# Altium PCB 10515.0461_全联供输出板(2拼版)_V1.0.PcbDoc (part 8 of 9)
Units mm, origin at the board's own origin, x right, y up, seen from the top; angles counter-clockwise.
Board outline 283.88 x 134.8 mm, 2 copper layers (Top Layer, Bottom Layer); 298 components, 0 nets, 1264 pads, 970 vias.
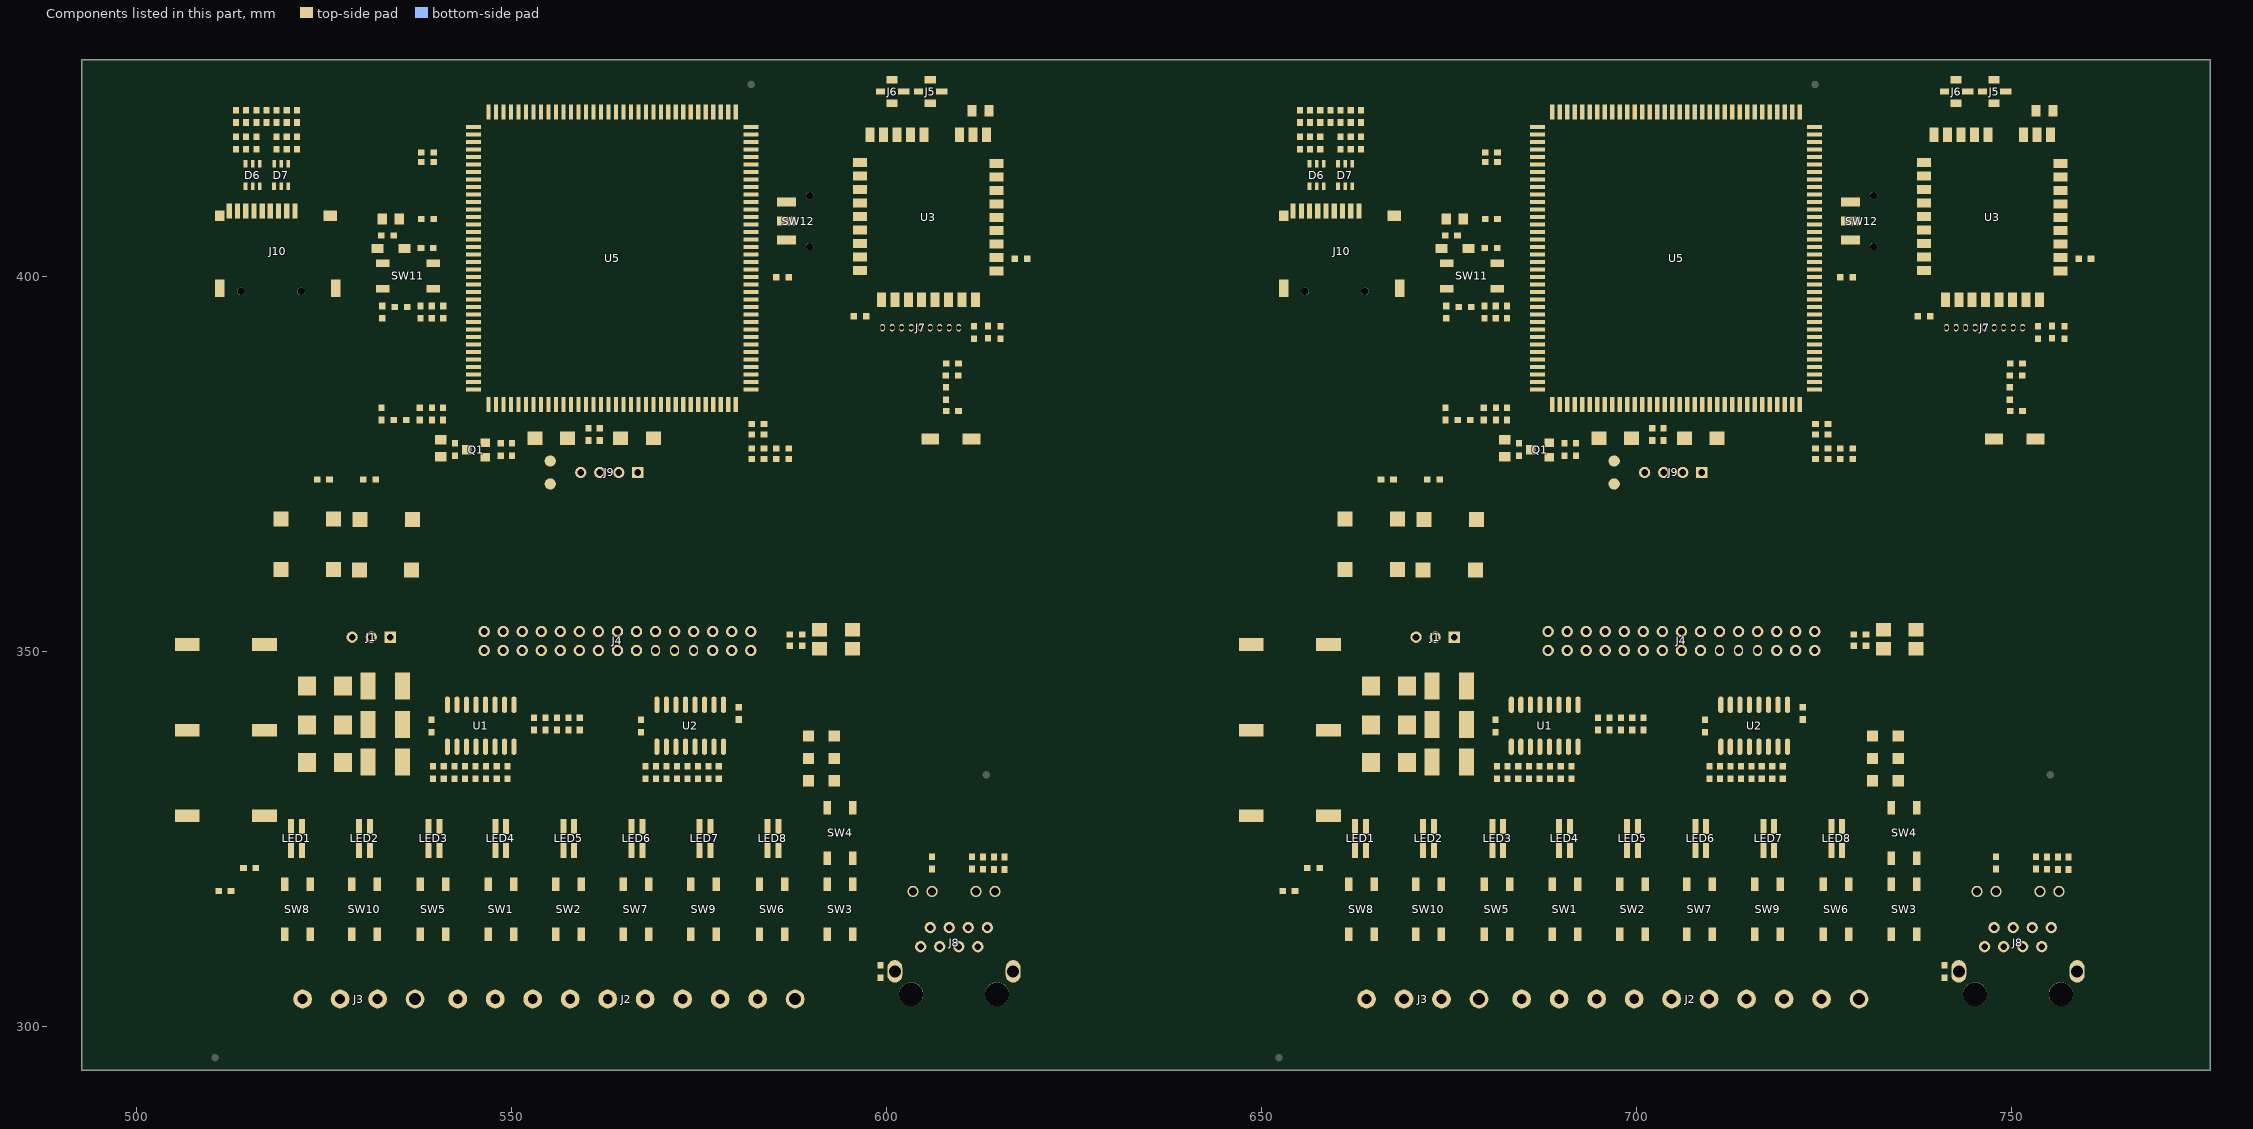
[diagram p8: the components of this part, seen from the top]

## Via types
v1: diameter 0.7, hole 0.4, Top Layer to Bottom Layer, tented both sides, 970 vias

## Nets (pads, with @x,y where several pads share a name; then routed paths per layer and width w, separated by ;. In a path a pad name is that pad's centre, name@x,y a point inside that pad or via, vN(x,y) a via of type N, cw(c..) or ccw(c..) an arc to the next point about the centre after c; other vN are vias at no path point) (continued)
copper on no net: (continued)
  Bottom Layer w0.8: v1(510.159,328.035) 513.541,328.035 514.223,327.353 v1(514.223,323.035) v1(514.223,322.273) ; v1@519.126,413.205 ccw(c519.619,413.205) 519.27,412.857 ; 520.319,411.808 519.875,412.253 ; 522.915,412.253 ccw(c522.915,413.216) v1@523.597,412.535 ; v1@523.526,412.535 ccw(c524.207,413.216) 524.207,412.253 ; v1@528.955,398.219 531.876,395.298 v1(531.876,380.693) ; v1@529.54,375.103 ccw(c530.2,375.13) v1(530.2,374.47) ; v1@529.555,374.505 cw(c531.002,373.058) 531.002,375.105 ; v1@529.555,375.07 ccw(c531.002,376.517) 531.002,374.47 ; v1@529.59,374.225 cw(c530.612,374.225) v1@530.178,375.15 ; v1@529.59,374.495 cw(c530.252,374.495) v1@530.195,375.155 ; v1@529.594,375.155 cw(c529.538,374.495) v1@530.2,374.495 ; v1@529.596,374.42 ccw(c529.51,375.105) v1(530.2,375.105) v1(530.2,374.47) ; v1@529.611,375.15 cw(c529.178,374.225) v1@530.2,374.225 ; v1@530.164,374.505 cw(c531.612,373.058) 531.612,375.105 ; v1@530.164,375.07 ccw(c531.612,376.517) 531.612,374.47 ; v1@530.193,374.42 cw(c530.28,375.105) v1(529.59,375.105) ; v1@530.25,374.472 ccw(c529.59,374.445) v1(529.59,375.105) ; v1(533.4,392.758) 533.4,395.806 530.606,398.6 530.606,410.538 ; 542.066,373.327 cw(c542.066,372.147) v1@542.901,372.981 ; v1@542.83,372.981 cw(c543.664,372.147) 543.664,373.327 ; v1(544.576,382.598) 544.576,379.804 545.211,379.169 v1(546.481,379.169) ; 549.91,373.327 551.815,371.422 563.753,371.422 ; 550.672,373.327 550.672,373.2 551.815,372.057 ; 551.815,371.838 cw(c553.36,371.838) v1@552.489,373.114 ; 551.815,373.327 551.815,372.057 ; 552.025,373.327 cw(c552.025,372.58) v1@552.553,373.108 ; 552.381,372.623 ccw(c551.93,373.073) v1@552.567,373.073 ; v1@552.482,373.108 cw(c553.01,372.58) 553.01,373.327 ; v1@552.498,373.119 cw(c552.844,372.264) 553.496,372.916 ; v1@552.517,373.023 ccw(c552.517,373.66) 552.968,373.21 ; v1@552.517,373.123 cw(c552.517,371.26) 553.835,372.577 ; v1@552.544,373.115 cw(c551.904,372.123) 553.085,372.123 ; v1@552.553,373.038 ccw(c551.267,374.323) 553.085,374.323 ; 553.085,372.311 553.085,373.327 ; 553.085,374.597 552.323,373.835 540.385,373.835 539.115,375.105 538.353,375.105 ; v1(553.085,376.756) 553.085,373.327 ; 554.355,372.057 553.085,373.327 ; 562.483,372.057 564.261,373.835 ; 563.817,372.502 ccw(c563.147,373.171) 563.96,373.656 ; 563.911,373.835 cw(c563.066,373.835) 563.664,373.238 cw(c564.261,372.64) 564.261,373.485 ; v1@567.421,375.994 ccw(c567.421,378.041) v1@568.868,376.594 ; v1@567.898,376.609 ccw(c568.833,377.012) v1(568.833,375.994) v1(567.309,375.994) ; v1(567.944,376.629) v1(567.309,375.994) ; v1@567.994,376.625 cw(c567.309,376.681) v1(567.309,375.994) ; 570.006,371.422 ccw(c570.006,372.602) v1@570.841,371.768 ; v1@570.77,371.768 ccw(c571.604,372.602) 571.604,371.422 ; 571.918,371.422 ccw(c571.918,373.036) v1@573.059,371.895 ; v1@572.989,371.895 ccw(c574.13,373.036) 574.13,371.422 ; 576.631,371.422 ccw(c576.631,372.299) v1@577.25,371.679 ; 576.814,371.93 cw(c576.814,371.314) v1@577.25,371.749 ; v1@577.18,371.679 ccw(c577.799,372.299) 577.799,371.422 ; v1@577.18,371.749 cw(c577.616,371.314) 577.616,371.93 ; 582.399,371.422 ccw(c582.399,373.036) v1@583.541,371.895 ; v1@583.47,371.895 ccw(c584.611,373.036) 584.611,371.422 ; 587.786,371.93 cw(c587.786,370.75) v1@588.621,371.584 ; v1@588.55,371.584 cw(c589.384,370.75) 589.384,371.93 ; v1@588.927,374.371 ccw(c590.222,375.666) 590.222,373.835 ; v1@588.991,373.87 cw(c590.438,372.423) 590.438,374.47 ; v1@589.012,374.402 cw(c588.391,374.459) v1(588.391,373.835) ; 591.85,371.93 cw(c591.85,370.75) v1@592.685,371.584 ; v1@592.614,371.584 cw(c593.448,370.75) 593.448,371.93 ; 595.3,371.422 ccw(c595.3,372.299) v1@595.919,371.679 ; 595.483,371.93 cw(c595.483,371.314) v1@595.919,371.749 ; v1@595.849,371.679 ccw(c596.468,372.299) 596.468,371.422 ; v1@595.849,371.749 cw(c596.285,371.314) 596.285,371.93 ; 599.679,374.47 cw(c599.679,372.423) v1@601.126,373.87 ; 600.112,371.93 cw(c600.112,370.316) v1@601.253,371.457 ; 600.441,374.47 cw(c600.441,372.423) v1@601.888,373.87 ; 600.493,371.422 ccw(c600.493,373.036) v1@601.634,371.895 ; 600.874,371.93 cw(c600.874,370.316) v1@602.015,371.457 ; v1@601.048,373.86 cw(c602.107,373.245) v1(602.107,374.47) ; v1@601.183,371.457 cw(c602.324,370.316) v1@602.324,371.93 ; v1@601.382,371.422 ccw(c601.382,373.036) v1@602.523,371.895 ; v1@601.567,371.892 ccw(c602.007,372.411) v1(602.488,371.93) ; v1@601.93,371.427 cw(c602.488,371.369) v1(602.488,371.93) ; v1@602.538,371.925 cw(c601.98,371.983) v1(601.98,371.422) ; v1(652.059,328.035) 655.441,328.035 656.123,327.353 v1(656.123,323.035) v1(656.123,322.273) ; v1@661.026,413.205 ccw(c661.518,413.205) 661.17,412.857 ; 662.219,411.808 661.774,412.253 ; 664.815,412.253 ccw(c664.815,413.216) v1@665.497,412.535 ; v1@665.426,412.535 ccw(c666.107,413.216) 666.107,412.253 ; v1@670.855,398.219 673.776,395.298 v1(673.776,380.693) ; v1@671.44,375.103 ccw(c672.1,375.13) v1(672.1,374.47) ; v1@671.455,374.505 cw(c672.902,373.058) 672.902,375.105 ; v1@671.455,375.07 ccw(c672.902,376.517) 672.902,374.47 ; v1@671.49,374.225 cw(c672.512,374.225) v1@672.078,375.15 ; v1@671.49,374.495 cw(c672.152,374.495) v1@672.095,375.155 ; v1@671.494,375.155 cw(c671.438,374.495) v1@672.1,374.495 ; v1@671.496,374.42 ccw(c671.41,375.105) v1(672.1,375.105) v1(672.1,374.47) ; v1@671.511,375.15 cw(c671.078,374.225) v1@672.1,374.225 ; v1@672.064,374.505 cw(c673.512,373.058) 673.512,375.105 ; v1@672.064,375.07 ccw(c673.512,376.517) 673.512,374.47 ; v1@672.093,374.42 cw(c672.18,375.105) v1(671.49,375.105) ; v1@672.15,374.472 ccw(c671.49,374.445) v1(671.49,375.105) ; v1(675.3,392.758) 675.3,395.806 672.506,398.6 672.506,410.538 ; 683.966,373.327 cw(c683.966,372.147) v1@684.801,372.981 ; v1@684.73,372.981 cw(c685.564,372.147) 685.564,373.327 ; v1(686.476,382.598) 686.476,379.804 687.111,379.169 v1(688.381,379.169) ; 691.81,373.327 693.715,371.422 705.653,371.422 ; 692.572,373.327 692.572,373.2 693.715,372.057 ; 693.715,371.838 cw(c695.26,371.838) v1@694.389,373.114 ; 693.715,373.327 693.715,372.057 ; 693.925,373.327 cw(c693.925,372.58) v1@694.453,373.108 ; 694.281,372.623 ccw(c693.83,373.073) v1@694.467,373.073 ; v1@694.382,373.108 cw(c694.91,372.58) 694.91,373.327 ; v1@694.398,373.119 cw(c694.744,372.264) 695.396,372.916 ; v1@694.417,373.023 ccw(c694.417,373.66) 694.868,373.21 ; v1@694.417,373.123 cw(c694.417,371.26) 695.735,372.577 ; v1@694.444,373.115 cw(c693.804,372.123) 694.985,372.123 ; v1@694.453,373.038 ccw(c693.167,374.323) 694.985,374.323 ; 694.985,372.311 694.985,373.327 ; 694.985,374.597 694.223,373.835 682.285,373.835 681.015,375.105 680.253,375.105 ; v1(694.985,376.756) 694.985,373.327 ; 696.255,372.057 694.985,373.327 ; 704.383,372.057 706.161,373.835 ; 705.717,372.502 ccw(c705.047,373.171) 705.86,373.656 ; 705.811,373.835 cw(c704.966,373.835) 705.564,373.238 cw(c706.161,372.64) 706.161,373.485 ; v1@709.321,375.994 ccw(c709.321,378.041) v1@710.768,376.594 ; v1@709.798,376.609 ccw(c710.733,377.012) v1(710.733,375.994) v1(709.209,375.994) ; v1(709.844,376.629) v1(709.209,375.994) ; v1@709.894,376.625 cw(c709.209,376.681) v1(709.209,375.994) ; 711.906,371.422 ccw(c711.906,372.602) v1@712.741,371.768 ; v1@712.67,371.768 ccw(c713.504,372.602) 713.504,371.422 ; 713.818,371.422 ccw(c713.818,373.036) v1@714.959,371.895 ; v1@714.889,371.895 ccw(c716.03,373.036) 716.03,371.422 ; 718.531,371.422 ccw(c718.531,372.299) v1@719.15,371.679 ; 718.714,371.93 cw(c718.714,371.314) v1@719.15,371.749 ; v1@719.08,371.679 ccw(c719.699,372.299) 719.699,371.422 ; v1@719.08,371.749 cw(c719.516,371.314) 719.516,371.93 ; 724.299,371.422 ccw(c724.299,373.036) v1@725.441,371.895 ; v1@725.37,371.895 ccw(c726.511,373.036) 726.511,371.422 ; 729.686,371.93 cw(c729.686,370.75) v1@730.521,371.584 ; v1@730.45,371.584 cw(c731.284,370.75) 731.284,371.93 ; v1@730.827,374.371 ccw(c732.122,375.666) 732.122,373.835 ; v1@730.891,373.87 cw(c732.338,372.423) 732.338,374.47 ; v1@730.912,374.402 cw(c730.291,374.459) v1(730.291,373.835) ; 733.75,371.93 cw(c733.75,370.75) v1@734.585,371.584 ; v1@734.514,371.584 cw(c735.348,370.75) 735.348,371.93 ; 737.2,371.422 ccw(c737.2,372.299) v1@737.819,371.679 ; 737.383,371.93 cw(c737.383,371.314) v1@737.819,371.749 ; v1@737.749,371.679 ccw(c738.368,372.299) 738.368,371.422 ; v1@737.749,371.749 cw(c738.185,371.314) 738.185,371.93 ; 741.579,374.47 cw(c741.579,372.423) v1@743.026,373.87 ; 742.012,371.93 cw(c742.012,370.316) v1@743.153,371.457 ; 742.341,374.47 cw(c742.341,372.423) v1@743.788,373.87 ; 742.393,371.422 ccw(c742.393,373.036) v1@743.534,371.895 ; 742.774,371.93 cw(c742.774,370.316) v1@743.915,371.457 ; v1@742.948,373.86 cw(c744.007,373.245) v1(744.007,374.47) ; v1@743.083,371.457 cw(c744.224,370.316) v1@744.224,371.93 ; v1@743.282,371.422 ccw(c743.282,373.036) v1@744.423,371.895 ; v1@743.467,371.892 ccw(c743.907,372.411) v1(744.388,371.93) ; v1@743.83,371.427 cw(c744.388,371.369) v1(744.388,371.93) ; v1@744.438,371.925 cw(c743.88,371.983) v1(743.88,371.422) ; 519.875,412.253 529.654,412.253 530.606,411.3 530.606,410.538 ; 519.875,412.253 519.176,412.951 v1(519.176,413.205) 519.176,412.189 519.557,411.808 529.336,411.808 530.606,410.538 ; v1(529.59,374.47) ccw(c529.59,375.13) 530.25,375.103 cw(c529.59,375.13) v1(529.59,374.47) ; v1(529.59,374.47) 538.988,374.47 540.131,373.327 ; v1(529.59,374.47) v1(530.2,374.47) ; v1(529.59,374.47) v1(529.59,375.105) ; v1(529.59,375.105) 538.353,375.105 ; 538.353,375.105 540.131,373.327 ; 540.131,373.327 553.085,373.327 ; 551.815,372.057 563.372,372.057 564.261,372.946 564.261,373.835 ; 551.815,372.057 553.085,373.327 ; 563.753,371.422 v1(601.98,371.422) ; 563.753,371.422 564.261,371.93 564.261,372.438 ; 564.261,372.438 564.769,371.93 v1(602.488,371.93) ; 564.261,372.438 564.261,373.835 ; 564.261,372.99 ccw(c563.416,372.99) 564.014,373.588 cw(c563.416,372.99) 564.261,372.99 ; 564.261,372.99 cw(c565.106,372.99) 564.508,373.588 ccw(c565.106,372.99) 564.261,372.99 ; v1(588.391,373.835) 589.026,374.47 v1(602.107,374.47) ; v1(588.391,373.835) v1(601.853,373.835) 602.107,374.089 v1(602.107,374.47) ; v1(601.98,371.422) v1(602.488,371.93) ; 661.774,412.253 671.553,412.253 672.506,411.3 672.506,410.538 ; 661.774,412.253 661.076,412.951 v1(661.076,413.205) 661.076,412.189 661.457,411.808 671.236,411.808 672.506,410.538 ; v1(671.49,374.47) ccw(c671.49,375.13) 672.15,375.103 cw(c671.49,375.13) v1(671.49,374.47) ; v1(671.49,374.47) 680.888,374.47 682.031,373.327 ; v1(671.49,374.47) v1(672.1,374.47) ; v1(671.49,374.47) v1(671.49,375.105) ; v1(671.49,375.105) 680.253,375.105 ; 680.253,375.105 682.031,373.327 ; 682.031,373.327 694.985,373.327 ; 693.715,372.057 705.272,372.057 706.161,372.946 706.161,373.835 ; 693.715,372.057 694.985,373.327 ; 705.653,371.422 v1(743.88,371.422) ; 705.653,371.422 706.161,371.93 706.161,372.438 ; 706.161,372.438 706.669,371.93 v1(744.388,371.93) ; 706.161,372.438 706.161,373.835 ; 706.161,372.99 ccw(c705.316,372.99) 705.914,373.588 cw(c705.316,372.99) 706.161,372.99 ; 706.161,372.99 cw(c707.006,372.99) 706.408,373.588 ccw(c707.006,372.99) 706.161,372.99 ; v1(730.291,373.835) 730.926,374.47 v1(744.007,374.47) ; v1(730.291,373.835) v1(743.753,373.835) 744.007,374.089 v1(744.007,374.47) ; v1(743.88,371.422) v1(744.388,371.93)
  Bottom Layer w1: 533.781,348.26 533.781,351.864 ; v1@546.608,323.416 v1(556.006,323.416) ; 675.681,348.26 675.681,351.864 ; v1@688.508,323.416 v1(697.906,323.416)
  Bottom Layer w1.5: v1@506.73,349.07 ccw(c507.395,349.735) 508.006,349.02 ; 507.336,348.152 ccw(c507.382,348.198) 507.382,348.133 ; 507.336,348.718 cw(c507.88,348.174) 507.88,348.943 ; 507.358,348.943 cw(c507.358,348.174) 507.902,348.718 ; 507.463,349.041 ccw(c507.7,349.278) 507.7,348.943 ; 507.792,348.943 ccw(c507.792,349.278) 508.029,349.041 ; 508.479,347.321 cw(c510.44,345.36) v1@510.44,348.133 ; 508.703,348.943 cw(c508.703,347.741) 509.553,348.591 ; v1@508.989,348.133 cw(c508.989,345.36) 510.95,347.321 ; 509.189,348.943 ccw(c509.189,349.278) 509.426,349.041 ; 509.27,348.708 cw(c509.27,348.447) 509.454,348.632 ; 509.594,348.492 cw(c509.409,348.308) 509.67,348.308 ; 509.751,348.133 cw(c509.751,345.36) 511.712,347.321 ; 510.384,347.321 cw(c512.345,345.36) 512.345,348.133 ; 511.146,347.321 cw(c513.107,345.36) 513.107,348.133 ; 519.811,347.038 519.811,355.547 521.017,356.754 ; 520.356,357.706 cw(c520.356,355.203) 522.126,356.973 ; 520.738,348.279 ccw(c521.091,348.632) 521.091,348.133 ; 520.951,348.133 ccw(c520.951,348.632) 521.304,348.279 ; 521.56,356.973 cw(c523.33,355.203) v1@523.33,357.706 ; v1@521.652,356.754 ccw(c521.652,359.04) 523.269,357.423 ; 521.667,357.445 ccw(c523.176,358.747) v1@523.176,356.754 ; 522.317,357.507 cw(c521.018,358.251) 521.018,356.754 ; 522.545,356.938 cw(c524.129,355.689) v1(524.129,357.706) ; 522.567,357.706 cw(c522.567,355.636) 524.031,357.1 ; 523.348,356.817 cw(c523.609,356.817) 523.424,357.001 ; 523.564,357.141 cw(c523.748,356.956) 523.748,357.217 ; 537.087,348.133 cw(c537.087,346.661) 538.128,347.702 ; 537.562,347.136 ccw(c537.799,347.373) 537.799,347.038 ; 537.562,347.702 cw(c538.603,346.661) v1@538.603,348.133 ; 537.891,347.038 ccw(c537.891,347.373) 538.128,347.136 ; 537.943,346.94 cw(c538.18,346.703) 538.18,347.038 ; 538.103,348.133 cw(c538.103,346.661) 539.144,347.702 ; 538.272,347.038 cw(c538.272,346.703) 538.509,346.94 ; 538.451,348.152 ccw(c538.497,348.198) 538.497,348.133 ; 538.578,347.136 ccw(c538.815,347.373) 538.815,347.038 ; 538.578,347.702 cw(c539.619,346.661) v1@539.619,348.133 ; 538.907,347.038 ccw(c538.907,347.373) 539.144,347.136 ; 538.971,348.133 ccw(c538.971,348.198) 539.017,348.152 ; 539.34,348.152 ccw(c539.386,348.198) 539.386,348.133 ; 539.86,348.133 ccw(c539.86,348.198) 539.906,348.152 ; 554.561,347.038 556.466,348.943 ; 555.371,347.038 556.466,348.133 ; 555.637,348.114 ccw(c553.666,350.086) 556.454,350.086 ; 556.459,350.077 cw(c554.289,347.337) 557.784,347.337 ; 556.458,352.618 cw(c553.255,349.415) 557.784,349.415 ; 556.459,350.096 ccw(c554.706,352.626) 557.784,352.626 ; 557.784,347.381 cw(c561.353,347.381) 559.014,350.077 ; 557.784,347.673 557.784,352.626 ; 557.784,349.647 cw(c561.985,349.647) 559.014,352.618 ; 559.006,350.086 556.466,350.086 ; 559.013,350.095 cw(c561.003,352.626) 557.784,352.626 ; v1@648.63,349.07 ccw(c649.295,349.735) 649.906,349.02 ; 649.236,348.152 ccw(c649.282,348.198) 649.282,348.133 ; 649.236,348.718 cw(c649.78,348.174) 649.78,348.943 ; 649.258,348.943 cw(c649.258,348.174) 649.802,348.718 ; 649.363,349.041 ccw(c649.6,349.278) 649.6,348.943 ; 649.692,348.943 ccw(c649.692,349.278) 649.929,349.041 ; 650.379,347.321 cw(c652.34,345.36) v1@652.34,348.133 ; 650.603,348.943 cw(c650.603,347.741) 651.453,348.591 ; v1@650.889,348.133 cw(c650.889,345.36) 652.85,347.321 ; 651.089,348.943 ccw(c651.089,349.278) 651.326,349.041 ; 651.17,348.708 cw(c651.17,348.447) 651.354,348.632 ; 651.494,348.492 cw(c651.309,348.308) 651.57,348.308 ; 651.651,348.133 cw(c651.651,345.36) 653.612,347.321 ; 652.284,347.321 cw(c654.245,345.36) 654.245,348.133 ; 653.046,347.321 cw(c655.007,345.36) 655.007,348.133 ; 661.711,347.038 661.711,355.547 662.917,356.754 ; 662.256,357.706 cw(c662.256,355.203) 664.026,356.973 ; 662.638,348.279 ccw(c662.991,348.632) 662.991,348.133 ; 662.851,348.133 ccw(c662.851,348.632) 663.204,348.279 ; 663.46,356.973 cw(c665.23,355.203) v1@665.23,357.706 ; v1@663.552,356.754 ccw(c663.552,359.04) 665.169,357.423 ; 663.567,357.445 ccw(c665.076,358.747) v1@665.076,356.754 ; 664.217,357.507 cw(c662.918,358.251) 662.918,356.754 ; 664.445,356.938 cw(c666.029,355.689) v1(666.029,357.706) ; 664.467,357.706 cw(c664.467,355.636) 665.931,357.1 ; 665.248,356.817 cw(c665.509,356.817) 665.324,357.001 ; 665.464,357.141 cw(c665.648,356.956) 665.648,357.217 ; 678.987,348.133 cw(c678.987,346.661) 680.028,347.702 ; 679.462,347.136 ccw(c679.699,347.373) 679.699,347.038 ; 679.462,347.702 cw(c680.503,346.661) v1@680.503,348.133 ; 679.791,347.038 ccw(c679.791,347.373) 680.028,347.136 ; 679.843,346.94 cw(c680.08,346.703) 680.08,347.038 ; 680.003,348.133 cw(c680.003,346.661) 681.044,347.702 ; 680.172,347.038 cw(c680.172,346.703) 680.409,346.94 ; 680.351,348.152 ccw(c680.397,348.198) 680.397,348.133 ; 680.478,347.136 ccw(c680.715,347.373) 680.715,347.038 ; 680.478,347.702 cw(c681.519,346.661) v1@681.519,348.133 ; 680.807,347.038 ccw(c680.807,347.373) 681.044,347.136 ; 680.871,348.133 ccw(c680.871,348.198) 680.917,348.152 ; 681.24,348.152 ccw(c681.286,348.198) 681.286,348.133 ; 681.76,348.133 ccw(c681.76,348.198) 681.806,348.152 ; 696.461,347.038 698.366,348.943 ; 697.271,347.038 698.366,348.133 ; 697.537,348.114 ccw(c695.566,350.086) 698.354,350.086 ; 698.358,352.618 cw(c695.155,349.415) 699.684,349.415 ; 698.359,350.077 cw(c696.189,347.337) 699.684,347.337 ; 698.359,350.096 ccw(c696.606,352.626) 699.684,352.626 ; 699.684,347.381 cw(c703.253,347.381) 700.914,350.077 ; 699.684,347.673 699.684,352.626 ; 699.684,349.647 cw(c703.885,349.647) 700.914,352.618 ; 700.906,350.086 698.366,350.086 ; 700.913,350.095 cw(c702.903,352.626) 699.684,352.626 ; v1@507.667,348.133 v1(508.762,347.038) 511.048,347.038 ; v1@507.667,348.133 v1(506.857,348.943) 509.143,348.943 511.048,347.038 ; v1@507.667,348.133 556.466,348.133 ; 511.048,347.038 518.541,347.038 ; 518.541,347.038 518.541,356.182 520.065,357.706 v1(521.97,357.706) ; 518.541,347.038 557.911,347.038 559.006,348.133 559.006,352.626 557.784,352.626 ; 521.017,356.754 v1@523.177,356.754 ; 521.017,356.754 v1(521.97,357.706) ; v1(521.97,357.706) v1(524.129,357.706) ; v1@523.177,356.754 v1(524.129,357.706) ; 556.466,348.133 556.466,348.943 ; 556.466,348.943 556.466,350.086 ; 556.466,350.086 556.466,352.626 557.784,352.626 ; v1@649.567,348.133 v1(650.662,347.038) 652.948,347.038 ; v1@649.567,348.133 v1(648.757,348.943) 651.043,348.943 652.948,347.038 ; v1@649.567,348.133 698.366,348.133 ; 652.948,347.038 660.441,347.038 ; 660.441,347.038 660.441,356.182 661.965,357.706 v1(663.87,357.706) ; 660.441,347.038 699.811,347.038 700.906,348.133 700.906,352.626 699.684,352.626 ; 662.917,356.754 v1@665.076,356.754 ; 662.917,356.754 v1(663.87,357.706) ; v1(663.87,357.706) v1(666.029,357.706) ; v1@665.076,356.754 v1(666.029,357.706) ; 698.366,348.133 698.366,348.943 ; 698.366,348.943 698.366,350.086 ; 698.366,350.086 698.366,352.626 699.684,352.626
  other v1: 515.62,299.578 657.52,299.578 604.012,299.847 745.912,299.847 536.769,300.048 678.669,300.048 525.399,300.086 530.733,300.086 561.975,300.086 566.674,300.086 576.199,300.086 585.851,300.086 595.63,300.086 610.616,300.086 620.776,300.086 667.299,300.086 672.633,300.086 703.875,300.086 708.574,300.086 718.099,300.086 727.751,300.086 737.53,300.086 752.516,300.086 762.676,300.086 552.517,300.302 694.417,300.302 544.703,300.594 616.204,300.594 686.603,300.594 758.104,300.594 592.455,301.61 734.355,301.61 599.253,301.699 741.153,301.699 508.508,302.118 619.252,302.118 650.408,302.118 761.152,302.118 608.203,302.626 750.103,302.626 597.729,303.985 739.629,303.985 593.665,305.001 735.565,305.001 591.312,305.166 608.203,305.166 733.212,305.166 750.103,305.166 516.449,305.763 658.349,305.763 620.589,305.89 762.489,305.89 575.183,306.017 580.965,306.017 717.083,306.017 722.865,306.017 596.646,306.182 738.546,306.182 594.36,306.906 736.26,306.906 558.613,307.033 700.513,307.033 514.925,307.16 656.825,307.16 556.641,307.198 560.959,307.198 564.515,307.198 570.357,307.198 698.541,307.198 702.859,307.198 706.415,307.198 712.257,307.198 614.426,309.23 756.326,309.23 620.081,310.589 761.981,310.589 508.829,311.097 650.729,311.097 602.996,312.278 744.896,312.278 617.541,312.621 759.441,312.621 508.829,313.51 552.577,313.51 650.729,313.51 694.477,313.51 602.809,314.653 744.709,314.653 506.797,314.78 616.017,314.78 648.697,314.78 757.917,314.78 601.285,315.923 743.185,315.923 619.76,316.85 761.66,316.85 509.337,318.082 651.237,318.082 601.285,319.733 743.185,319.733 620.776,319.898 762.676,319.898 600.583,322.146 601.793,322.146 742.483,322.146 743.693,322.146 620.081,322.781 761.981,322.781 507.619,322.946 649.519,322.946 587.248,323.162 729.148,323.162 546.735,323.416 688.635,323.416 588.391,323.454 730.291,323.454 587.569,325.321 589.093,325.321 729.469,325.321 730.993,325.321 602.301,325.702 621.097,325.702 744.201,325.702 762.997,325.702 610.937,327.48 752.837,327.48 587.569,328.623 729.469,328.623 589.026,329.55 730.926,329.55 586.553,330.909 728.453,330.909 602.234,331.074 744.134,331.074 580.136,332.09 722.036,332.09 594.868,332.712 736.768,332.712 537.591,334.122 580.136,334.122 679.491,334.122 722.036,334.122 602.301,334.211 744.201,334.211 610.937,334.973 752.837,334.973 597.729,335.735 739.629,335.735 601.793,336.751 743.693,336.751 537.785,337.259 679.685,337.259 551.688,337.439 693.588,337.439 580.457,337.894 722.357,337.894 543.373,339.344 685.273,339.344 586.105,339.418 595.189,339.418 728.005,339.418 737.089,339.418 537.277,339.545 679.177,339.545 538.032,340.726 679.932,340.726 610.937,342.085 752.837,342.085 596.011,342.25 737.911,342.25 586.553,342.339 728.453,342.339 583.629,342.72 725.528,342.72 512.699,343.266 654.599,343.266 591.125,344.117 733.025,344.117 605.028,344.79 746.928,344.79 588.077,345.006 729.977,345.006 545.211,345.022 687.111,345.022 593.979,345.298 601.472,345.298 735.879,345.298 743.372,345.298 538.226,346.657 680.126,346.657 510.667,347.038 595.189,347.038 652.567,347.038 737.089,347.038 590.423,347.33 732.323,347.33 537.845,347.419 538.861,347.419 587.569,347.419 679.745,347.419 680.761,347.419 729.469,347.419 609.413,347.927 751.313,347.927 511.556,348.181 653.456,348.181 509.27,348.308 510.413,348.308 651.17,348.308 652.313,348.308 526.161,348.346 604.647,348.346 668.061,348.346 746.547,348.346 507.619,348.435 538.734,348.435 649.519,348.435 680.634,348.435 521.021,348.562 662.921,348.562 519.521,349.191 661.421,349.191 507.746,349.324 509.143,349.324 649.646,349.324 651.043,349.324 602.301,349.959 744.201,349.959 512.385,350.647 654.285,350.647 605.857,351.61 747.757,351.61 512.385,353.822 654.285,353.822 517.465,354.076 659.365,354.076 602.301,354.404 744.201,354.404 609.092,354.442 750.992,354.442 595.376,356.474 737.276,356.474 514.925,356.563 656.825,356.563 521.843,356.69 522.859,356.69 663.743,356.69 664.759,356.69 523.748,356.817 665.648,356.817 525.399,356.982 527.431,356.982 533.527,356.982 667.299,356.982 669.331,356.982 675.427,356.982 530.673,357.124 672.573,357.124 507.619,357.49 649.519,357.49 522.986,357.706 664.886,357.706 526.161,358.14 668.061,358.14 528.447,358.267 531.876,358.267 533.527,358.267 670.347,358.267 673.776,358.267 675.427,358.267 512.385,359.103 654.285,359.103 595.697,360.246 737.597,360.246 592.141,361.389 734.041,361.389 509.651,362.57 651.551,362.57 528.133,364.31 670.033,364.31 595.189,364.564 737.089,364.564 515.433,365.453 657.333,365.453 508.381,368.158 650.281,368.158 513.08,368.666 654.98,368.666 593.665,370.025 735.565,370.025 528.133,370.914 670.033,370.914 588.585,371.549 592.649,371.549 605.857,371.549 730.485,371.549 734.549,371.549 747.757,371.549 510.54,371.714 577.215,371.714 595.884,371.714 652.44,371.714 719.115,371.714 737.784,371.714 570.805,371.803 712.705,371.803 573.024,371.93 583.505,371.93 601.599,371.93 714.924,371.93 725.405,371.93 743.499,371.93 608.076,372.73 749.976,372.73 542.865,372.946 617.855,372.946 684.765,372.946 759.755,372.946 552.517,373.073 694.417,373.073 612.969,373.581 754.869,373.581 518.989,374.47 609.921,374.47 660.889,374.47 751.821,374.47 608.076,374.762 749.976,374.762 514.417,375.486 656.317,375.486 507.305,375.74 649.205,375.74 615.509,375.867 757.409,375.867 527.939,376.286 669.839,376.286 568.833,376.629 710.733,376.629 534.162,376.794 592.709,376.794 676.062,376.794 734.609,376.794 595.697,377.01 737.597,377.01 618.871,377.302 760.771,377.302 537.785,377.518 679.685,377.518 526.288,377.81 614.934,377.81 668.188,377.81 756.834,377.81 512.572,378.318 654.472,378.318 534.162,378.826 537.083,378.826 617.093,378.826 676.062,378.826 678.983,378.826 758.993,378.826 544.389,378.915 686.289,378.915 521.208,379.334 542.798,379.334 548.132,379.334 595.503,379.334 663.108,379.334 684.698,379.334 690.032,379.334 737.403,379.334 549.469,379.55 592.141,379.55 691.369,379.55 734.041,379.55 517.779,379.842 659.679,379.842 527.625,380.058 669.525,380.058 612.775,380.35 754.675,380.35 617.033,381.582 619.573,381.582 758.933,381.582 761.473,381.582 615.001,382.471 756.901,382.471 542.865,382.725 684.765,382.725 526.542,382.89 668.442,382.89 529.463,383.398 671.363,383.398 509.337,383.614 651.237,383.614 506.984,383.906 648.884,383.906 614.807,384.414 756.707,384.414 515.941,384.503 657.841,384.503 611.953,384.757 753.853,384.757 542.357,385.138 684.257,385.138 548.767,385.91 553.593,385.91 690.667,385.91 695.493,385.91 521.208,385.938 557.276,385.938 663.108,385.938 699.176,385.938 617.033,386.027 758.933,386.027 569.281,386.408 711.181,386.408 530.673,386.789 672.573,386.789 577.977,386.954 719.877,386.954 535.245,387.17 677.145,387.17 512.385,387.805 654.285,387.805 614.68,387.97 756.58,387.97 618.049,388.44 759.949,388.44 508.321,388.694 518.481,388.694 650.221,388.694 660.381,388.694 538.293,388.948 680.193,388.948 533.4,388.986 540.893,388.986 567.563,388.986 572.77,388.986 675.3,388.986 682.793,388.986 709.463,388.986 714.67,388.986 523.875,390.002 665.775,390.002 555.565,390.472 697.465,390.472 619.76,391.234 761.66,391.234 584.013,391.361 725.913,391.361 617.541,392.123 759.441,392.123 535.245,392.25 677.145,392.25 559.054,392.542 568.452,392.542 700.954,392.542 710.352,392.542 530.673,392.758 672.573,392.758 578.425,392.885 720.325,392.885 514.417,393.012 656.317,393.012 584.2,393.558 726.1,393.558 550.672,394.066 692.572,394.066 555.625,394.574 697.525,394.574 588.585,394.663 730.485,394.663 507.305,394.917 649.205,394.917 591.312,395.082 733.212,395.082 573.853,395.298 715.753,395.298 519.811,396.098 661.711,396.098 590.617,397.457 732.517,397.457 584.013,397.838 725.913,397.838 507.305,398.473 649.205,398.473 542.163,398.638 565.531,398.638 684.063,398.638 707.431,398.638 517.652,399.654 659.552,399.654 535.245,399.87 677.145,399.87 530.673,399.997 532.705,399.997 537.785,399.997 672.573,399.997 674.605,399.997 679.685,399.997 575.377,400.124 717.277,400.124 569.341,400.162 590.931,400.162 711.241,400.162 732.831,400.162 523.561,401.267 665.461,401.267 558.038,401.686 699.938,401.686 530.673,401.775 672.573,401.775 542.357,401.902 684.257,401.902 516.449,402.029 658.349,402.029 526.288,402.194 668.188,402.194 509.524,402.702 586.867,402.702 651.424,402.702 728.767,402.702 584.013,402.918 725.913,402.918 549.529,403.21 691.429,403.21 513.401,403.426 565.725,403.426 655.301,403.426 707.625,403.426 541.528,403.718 683.428,403.718 542.357,404.188 684.257,404.188 507.492,404.226 520.827,404.226 649.392,404.226 662.727,404.226 526.288,404.734 668.188,404.734 572.329,405.204 714.229,405.204 523.24,405.75 665.14,405.75 557.089,406.093 698.989,406.093 575.945,406.258 717.845,406.258 530.479,406.766 551.815,406.766 672.379,406.766 693.715,406.766 508.321,407.49 650.221,407.49 567.757,407.617 709.657,407.617 568.452,407.782 710.352,407.782 590.109,408.506 732.009,408.506 530.673,409.014 542.163,409.014 672.573,409.014 684.063,409.014 506.797,410.03 648.697,410.03 548.386,410.322 690.286,410.322 516.067,410.604 517.779,410.604 657.967,410.604 659.679,410.604 540.512,410.83 682.412,410.83 575.377,411.3 717.277,411.3 508.635,411.846 533.019,411.846 584.835,411.846 650.535,411.846 674.919,411.846 726.735,411.846 554.041,411.935 695.941,411.935 537.785,412.316 679.685,412.316 510.861,412.57 523.561,412.57 652.761,412.57 665.461,412.57 557.403,412.862 699.303,412.862 514.35,412.951 656.25,412.951 578.104,413.37 720.004,413.37 525.593,413.459 667.493,413.459 566.741,413.713 708.641,413.713 542.29,413.878 684.19,413.878 586.553,414.348 728.453,414.348 506.603,414.386 528.447,414.386 648.503,414.386 670.347,414.386 571.821,414.602 713.721,414.602 532.197,414.729 591.125,414.729 674.097,414.729 733.025,414.729 514.355,415.867 515.327,415.867 516.299,415.867 517.271,415.867 656.255,415.867 657.227,415.867 658.199,415.867 659.171,415.867 584.835,415.91 726.735,415.91 532.705,416.253 560.645,416.253 589.601,416.253 674.605,416.253 702.545,416.253 731.501,416.253 509.337,416.888 651.237,416.888 525.78,416.926 667.68,416.926 529.082,417.434 670.982,417.434 523.24,417.942 665.14,417.942 566.741,418.031 708.641,418.031 550.993,418.158 692.893,418.158 530.987,418.45 576.199,418.45 672.887,418.45 718.099,418.45 538.48,418.958 541.274,418.958 680.38,418.958 683.174,418.958 535.753,419.301 677.653,419.301 510.921,419.466 652.821,419.466 569.789,419.682 711.689,419.682 584.073,419.974 725.973,419.974 506.289,420.317 648.189,420.317 524.256,420.482 529.59,420.482 533.908,420.482 666.156,420.482 671.49,420.482 675.808,420.482 606.791,420.937 748.691,420.937 544.897,421.714 686.797,421.714 525.526,422.006 535.051,422.006 539.496,422.006 667.426,422.006 676.951,422.006 681.396,422.006 510.353,422.095 652.253,422.095 506.73,422.514 543.687,422.514 648.63,422.514 685.587,422.514 581.981,422.603 723.881,422.603 530.165,422.73 672.065,422.73 509.016,423.53 650.916,423.53 510.861,424.889 652.761,424.889 507.619,425.054 649.519,425.054 509.27,426.578 651.17,426.578 506.797,427.302 648.697,427.302 511.369,427.429 653.269,427.429

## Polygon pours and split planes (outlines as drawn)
no net on Top Layer "Top Layer-No Net" (hatched 90Degree grid 0.508 track 0.508, remove dead copper, pour order 1001): 647.868,420.99 647.868,428.752 647.995,428.879 668.008,428.879 668.188,428.699 668.188,423.403 666.283,421.498 648.287,421.498 647.868,421.079
no net on Top Layer "Top Layer-No Net" (hatched 90Degree grid 0.508 track 0.508, remove dead copper, pour order 1000): 647.995,300.556 649.773,298.778 762.93,298.778 764.2,300.048 764.2,325.575 763.565,326.21 753.659,326.21 753.024,326.845 753.024,355.293 752.262,356.055 743.118,356.055 743.118,369.898 743.626,370.406 761.025,370.406 761.66,371.041 761.66,415.11 761.406,415.364 757.723,415.364 757.469,415.11 757.469,395.552 756.834,394.917 734.355,394.917 733.466,395.806 733.466,416.126 732.831,416.761 726.735,416.761 726.354,417.142 726.354,422.603 725.846,423.111 649.9,423.111 647.868,421.079
no net on Top Layer "Top Layer-No Net" (hatched 90Degree grid 0.508 track 0.508, remove dead copper, pour order 1001): 505.968,420.99 505.968,428.752 506.095,428.879 526.108,428.879 526.288,428.699 526.288,423.403 524.383,421.498 506.387,421.498 505.968,421.079
no net on Top Layer "Top Layer-No Net" (hatched 90Degree grid 0.508 track 0.508, remove dead copper, pour order 1000): 506.095,300.556 507.873,298.778 621.03,298.778 622.3,300.048 622.3,325.575 621.665,326.21 611.759,326.21 611.124,326.845 611.124,355.293 610.362,356.055 601.218,356.055 601.218,369.898 601.726,370.406 619.125,370.406 619.76,371.041 619.76,415.11 619.506,415.364 615.823,415.364 615.569,415.11 615.569,395.552 614.934,394.917 592.455,394.917 591.566,395.806 591.566,416.126 590.931,416.761 584.835,416.761 584.454,417.142 584.454,422.603 583.946,423.111 508,423.111 505.968,421.079
no net on Bottom Layer "Top Layer-No Net" (hatched 90Degree grid 0.508 track 0.508, remove dead copper, pour order 1003): 647.995,421.206 647.995,428.879 708.394,428.879 708.828,428.445 708.828,424.328 709.717,423.439 709.717,423.149 709.59,423.022 652.545,423.022 650.729,421.206 647.995,421.206
no net on Bottom Layer "Top Layer-No Net" (hatched 90Degree grid 0.508 track 0.508, remove dead copper, pour order 1002): 647.995,300.884 649.773,299.106 762.93,299.106 764.2,300.376 764.2,325.903 763.565,326.538 753.659,326.538 753.024,327.173 753.024,355.621 752.262,356.383 743.118,356.383 743.118,370.226 743.626,370.734 760.898,370.66 761.66,371.422 761.66,415.438 761.406,415.692 757.723,415.692 757.469,415.438 757.469,395.88 756.834,395.245 734.355,395.245 733.466,396.134 733.466,416.454 732.831,417.089 726.735,417.089 726.354,417.47 726.354,422.931 725.846,423.439 649.9,423.439 647.995,421.46
no net on Bottom Layer "Top Layer-No Net" (hatched 90Degree grid 0.508 track 0.508, remove dead copper, pour order 1003): 506.095,421.206 506.095,428.879 566.494,428.879 566.928,428.445 566.928,424.328 567.817,423.439 567.817,423.149 567.69,423.022 510.645,423.022 508.829,421.206 506.095,421.206
no net on Bottom Layer "Top Layer-No Net" (hatched 90Degree grid 0.508 track 0.508, remove dead copper, pour order 1002): 506.095,300.884 507.873,299.106 621.03,299.106 622.3,300.376 622.3,325.903 621.665,326.538 611.759,326.538 611.124,327.173 611.124,355.621 610.362,356.383 601.218,356.383 601.218,370.226 601.726,370.734 618.998,370.66 619.76,371.422 619.76,415.438 619.506,415.692 615.823,415.692 615.569,415.438 615.569,395.88 614.934,395.245 592.455,395.245 591.566,396.134 591.566,416.454 590.931,417.089 584.835,417.089 584.454,417.47 584.454,422.931 583.946,423.439 508,423.439 506.095,421.46

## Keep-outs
Keep-Out Layer:
  circle w0.127: c641.525,363.679 r2
  circle w0.127: c641.525,407.679 r2
  circle w0.127: c641.525,354.079 r2
  circle w0.127: c641.525,300.079 r2
  circle w0.127: c769.525,407.679 r2
  circle w0.127: c769.525,363.679 r2
  circle w0.127: c769.525,354.079 r2
  circle w0.127: c769.525,300.079 r2
  circle w0.127: c758.857,340.15 r1
  circle w0.127: c763.048,340.15 r1
  circle w0.127: c763.048,329.228 r1
  circle w0.127: c758.857,329.228 r1
  circle w0.127: c499.625,363.679 r2
  circle w0.127: c499.625,407.679 r2
  circle w0.127: c499.625,354.079 r2
  circle w0.127: c499.625,300.079 r2
  circle w0.127: c627.625,407.679 r2
  circle w0.127: c627.625,363.679 r2
  circle w0.127: c627.625,354.079 r2
  circle w0.127: c627.625,300.079 r2
  circle w0.127: c616.957,340.15 r1
  circle w0.127: c621.148,340.15 r1
  circle w0.127: c621.148,329.228 r1
  circle w0.127: c616.957,329.228 r1
  circle w0.127: c3926.224,1495.132 r0.05
  circle w0.127: c3929.724,1495.132 r0.05
  circle w0.127: c3946.224,1495.132 r0.05
  circle w0.127: c3949.724,1495.132 r0.05
  circle w0.127: c3926.224,1495.132 r0.25
  circle w0.127: c3929.724,1495.132 r0.25
  circle w0.127: c3946.224,1495.132 r0.25
  circle w0.127: c3949.724,1495.132 r0.25
  circle w0.127: c3937.974,1503.382 r1
  circle w0.127: c3929.724,1491.632 r0.05
  circle w0.127: c3926.224,1491.632 r0.05
  circle w0.127: c3949.724,1491.632 r0.05
  circle w0.127: c3946.224,1491.632 r0.05
  circle w0.127: c3926.224,1491.632 r0.25
  circle w0.127: c3929.724,1491.632 r0.25
  circle w0.127: c3946.224,1491.632 r0.25
  circle w0.127: c3949.724,1491.632 r0.25
  circle w0.127: c3955.045,1486.311 r1
  circle w0.127: c3920.903,1486.311 r1
  circle w0.127: c3927.974,1493.382 r1.093
  circle w0.127: c3947.974,1493.382 r1.093
  circle w0.127: c3927.974,1493.382 r1.292
  circle w0.127: c3947.974,1493.382 r1.292
  circle w0.127: c3927.974,1493.382 r1.3
  circle w0.127: c3947.974,1493.382 r1.3
  circle w0.127: c3854.974,1503.882 r0.3
  circle w0.127: c3852.974,1503.882 r0.3
  circle w0.127: c3850.974,1503.882 r0.3
  circle w0.127: c3848.974,1503.882 r0.3
  circle w0.127: c3846.974,1503.882 r0.3
  circle w0.127: c3844.974,1503.882 r0.3
  circle w0.127: c3842.974,1503.882 r0.3
  circle w0.127: c3840.974,1503.882 r0.3
  circle w0.127: c3838.974,1503.882 r0.3
  circle w0.127: c3836.974,1503.882 r0.3
  circle w0.127: c3834.974,1503.882 r0.3
  circle w0.127: c3832.974,1503.882 r0.3
  circle w0.127: c3866.974,1503.382 r1
  circle w0.127: c3822.974,1503.382 r1
  circle w0.127: c3822.974,1486.311 r0.85
  circle w0.127: c3252.108,957.795 r0.05
  circle w0.127: c3255.608,957.795 r0.05
  circle w0.127: c3272.108,957.795 r0.05
  circle w0.127: c3275.608,957.795 r0.05
  circle w0.127: c3252.108,957.795 r0.25
  circle w0.127: c3255.608,957.795 r0.25
  circle w0.127: c3272.108,957.795 r0.25
  circle w0.127: c3275.608,957.795 r0.25
  circle w0.127: c3263.858,966.045 r1
  circle w0.127: c3255.608,954.295 r0.05
  circle w0.127: c3252.108,954.295 r0.05
  circle w0.127: c3275.608,954.295 r0.05
  circle w0.127: c3272.108,954.295 r0.05
  circle w0.127: c3252.108,954.295 r0.25
  circle w0.127: c3255.608,954.295 r0.25
  circle w0.127: c3272.108,954.295 r0.25
  circle w0.127: c3275.608,954.295 r0.25
  circle w0.127: c3280.929,948.974 r1
  circle w0.127: c3246.787,948.974 r1
  circle w0.127: c3253.858,956.045 r1.093
  circle w0.127: c3273.858,956.045 r1.093
  circle w0.127: c3253.858,956.045 r1.292
  circle w0.127: c3273.858,956.045 r1.292
  circle w0.127: c3253.858,956.045 r1.3
  circle w0.127: c3273.858,956.045 r1.3
  circle w0.127: c3180.858,966.545 r0.3
  circle w0.127: c3178.858,966.545 r0.3
  circle w0.127: c3176.858,966.545 r0.3
  circle w0.127: c3174.858,966.545 r0.3
  circle w0.127: c3172.858,966.545 r0.3
  circle w0.127: c3170.858,966.545 r0.3
  circle w0.127: c3168.858,966.545 r0.3
  circle w0.127: c3166.858,966.545 r0.3
  circle w0.127: c3164.858,966.545 r0.3
  circle w0.127: c3162.858,966.545 r0.3
  circle w0.127: c3160.858,966.545 r0.3
  circle w0.127: c3158.858,966.545 r0.3
  circle w0.127: c3192.858,966.045 r1
  circle w0.127: c3148.858,966.045 r1
  circle w0.127: c3148.858,948.974 r0.85
  lines w0.127: 492.633,308.737 503.682,308.737 503.682,325.374 492.633,325.374 ; 492.633,413.385 503.682,413.385 503.682,428.879 ; 623.568,428.879 623.568,413.385 634.617,413.385 ; 634.533,308.737 645.582,308.737 645.582,325.374 634.533,325.374 ; 634.533,413.385 645.582,413.385 645.582,428.879 ; 634.617,308.737 623.568,308.737 623.568,325.374 634.617,325.374 ; 765.468,428.879 765.468,413.385 776.517,413.385 ; 776.517,308.737 765.468,308.737 765.468,325.374 776.517,325.374 ; 3156.358,965.545 3156.358,964.945 3156.858,964.945 3156.858,968.445 3156.358,968.445 3156.358,967.845 ; 3156.858,965.545 3155.858,965.545 3155.858,963.645 3183.858,963.645 3183.858,965.545 3182.858,965.545 ; 3156.858,967.845 3155.858,967.845 3155.858,969.045 3183.858,969.045 3183.858,967.845 3182.858,967.845 ; 3183.358,965.545 3183.358,964.945 3182.858,964.945 3182.858,968.445 3183.358,968.445 3183.358,967.845 ; 3251.933,953.795 3251.933,951.345 3253.283,951.345 3253.283,953.795 ; 3251.933,958.295 3251.933,960.745 3253.283,960.745 3253.283,958.295 ; 3252.233,953.295 3252.983,953.295 ; 3252.233,953.395 3252.983,953.395 ; 3252.233,953.795 3252.233,952.845 3252.983,952.845 3252.983,953.795 ; 3252.233,958.295 3252.233,959.245 3252.983,959.245 3252.983,958.295 ; 3252.233,958.695 3252.983,958.695 ; 3252.233,958.795 3252.983,958.795 ; 3254.433,953.795 3254.433,951.345 3255.783,951.345 3255.783,953.795 ; 3254.433,958.295 3254.433,960.745 3255.783,960.745 3255.783,958.295 ; 3254.733,953.295 3255.483,953.295 ; 3254.733,953.395 3255.483,953.395 ; 3254.733,953.795 3254.733,952.845 3255.483,952.845 3255.483,953.795 ; 3254.733,958.295 3254.733,959.245 3255.483,959.245 3255.483,958.295 ; 3254.733,958.695 3255.483,958.695 ; 3254.733,958.795 3255.483,958.795 ; 3271.933,953.795 3271.933,951.345 3273.283,951.345 3273.283,953.795 ; 3271.933,958.295 3271.933,960.745 3273.283,960.745 3273.283,958.295 ; 3272.233,953.295 3272.983,953.295 ; 3272.233,953.395 3272.983,953.395 ; 3272.233,953.795 3272.233,952.845 3272.983,952.845 3272.983,953.795 ; 3272.233,958.295 3272.233,959.245 3272.983,959.245 3272.983,958.295 ; 3272.233,958.695 3272.983,958.695 ; 3272.233,958.795 3272.983,958.795 ; 3274.433,953.795 3274.433,951.345 3275.783,951.345 3275.783,953.795 ; 3274.433,958.295 3274.433,960.745 3275.783,960.745 3275.783,958.295 ; 3274.733,953.295 3275.483,953.295 ; 3274.733,953.395 3275.483,953.395 ; 3274.733,953.795 3274.733,952.845 3275.483,952.845 3275.483,953.795 ; 3274.733,958.295 3274.733,959.245 3275.483,959.245 3275.483,958.295 ; 3274.733,958.695 3275.483,958.695 ; 3274.733,958.795 3275.483,958.795 ; 3830.474,1502.882 3830.474,1502.282 3830.974,1502.282 3830.974,1505.782 3830.474,1505.782 3830.474,1505.182 ; 3830.974,1502.882 3829.974,1502.882 3829.974,1500.982 3857.974,1500.982 3857.974,1502.882 3856.974,1502.882 ; 3830.974,1505.182 3829.974,1505.182 3829.974,1506.382 3857.974,1506.382 3857.974,1505.182 3856.974,1505.182 ; 3857.474,1502.882 3857.474,1502.282 3856.974,1502.282 3856.974,1505.782 3857.474,1505.782 3857.474,1505.182 ; 3926.049,1491.132 3926.049,1488.682 3927.399,1488.682 3927.399,1491.132 ; 3926.049,1495.632 3926.049,1498.082 3927.399,1498.082 3927.399,1495.632 ; 3926.349,1490.632 3927.099,1490.632 ; 3926.349,1490.732 3927.099,1490.732 ; 3926.349,1491.132 3926.349,1490.182 3927.099,1490.182 3927.099,1491.132 ; 3926.349,1495.632 3926.349,1496.582 3927.099,1496.582 3927.099,1495.632 ; 3926.349,1496.032 3927.099,1496.032 ; 3926.349,1496.132 3927.099,1496.132 ; 3928.549,1491.132 3928.549,1488.682 3929.899,1488.682 3929.899,1491.132 ; 3928.549,1495.632 3928.549,1498.082 3929.899,1498.082 3929.899,1495.632 ; 3928.849,1490.632 3929.599,1490.632 ; 3928.849,1490.732 3929.599,1490.732 ; 3928.849,1491.132 3928.849,1490.182 3929.599,1490.182 3929.599,1491.132 ; 3928.849,1495.632 3928.849,1496.582 3929.599,1496.582 3929.599,1495.632 ; 3928.849,1496.032 3929.599,1496.032 ; 3928.849,1496.132 3929.599,1496.132 ; 3946.049,1491.132 3946.049,1488.682 3947.399,1488.682 3947.399,1491.132 ; 3946.049,1495.632 3946.049,1498.082 3947.399,1498.082 3947.399,1495.632 ; 3946.349,1490.632 3947.099,1490.632 ; 3946.349,1490.732 3947.099,1490.732 ; 3946.349,1491.132 3946.349,1490.182 3947.099,1490.182 3947.099,1491.132 ; 3946.349,1495.632 3946.349,1496.582 3947.099,1496.582 3947.099,1495.632 ; 3946.349,1496.032 3947.099,1496.032 ; 3946.349,1496.132 3947.099,1496.132 ; 3948.549,1491.132 3948.549,1488.682 3949.899,1488.682 3949.899,1491.132 ; 3948.549,1495.632 3948.549,1498.082 3949.899,1498.082 3949.899,1495.632 ; 3948.849,1490.632 3949.599,1490.632 ; 3948.849,1490.732 3949.599,1490.732 ; 3948.849,1491.132 3948.849,1490.182 3949.599,1490.182 3949.599,1491.132 ; 3948.849,1495.632 3948.849,1496.582 3949.599,1496.582 3949.599,1495.632 ; 3948.849,1496.032 3949.599,1496.032 ; 3948.849,1496.132 3949.599,1496.132 ; 492.633,294.079 492.633,428.879 503.125,428.879 624.125,428.879 634.617,428.879 634.617,294.079 624.125,294.079 503.125,294.079 492.633,294.079 ; 539.115,356.563 539.115,369.898 588.137,369.898 588.137,356.563 539.115,356.563 ; 601.472,356.563 601.472,369.898 622.554,369.898 622.554,356.563 622.554,343.736 612.14,343.736 612.14,355.928 ccw(c611.505,355.928) 611.505,356.563 601.472,356.563 ; 634.533,294.079 634.533,428.879 645.025,428.879 766.025,428.879 776.517,428.879 776.517,294.079 766.025,294.079 645.025,294.079 634.533,294.079 ; 681.015,356.563 681.015,369.898 730.037,369.898 730.037,356.563 681.015,356.563 ; 743.372,356.563 743.372,369.898 764.454,369.898 764.454,356.563 764.454,343.736 754.04,343.736 754.04,355.928 ccw(c753.405,355.928) 753.405,356.563 743.372,356.563 ; 3143.858,945.045 3283.858,945.045 3283.858,970.045 3143.858,970.045 3143.858,945.045 ; 3157.458,964.145 3157.458,967.645 3159.983,967.645 3159.983,968.545 3179.733,968.545 3179.733,967.645 3182.258,967.645 3182.258,964.145 3157.458,964.145 ; 3251.608,953.995 ccw(c3251.808,953.995) 3251.808,953.795 3255.908,953.795 ccw(c3255.908,953.995) 3256.108,953.995 3256.108,958.095 ccw(c3255.908,958.095) 3255.908,958.295 3251.808,958.295 ccw(c3251.808,958.095) 3251.608,958.095 3251.608,953.995 ; 3271.608,953.995 ccw(c3271.808,953.995) 3271.808,953.795 3275.908,953.795 ccw(c3275.908,953.995) 3276.108,953.995 3276.108,958.095 ccw(c3275.908,958.095) 3275.908,958.295 3271.808,958.295 ccw(c3271.808,958.095) 3271.608,958.095 3271.608,953.995 ; 3817.974,1482.382 3957.974,1482.382 3957.974,1507.382 3817.974,1507.382 3817.974,1482.382 ; 3831.574,1501.482 3831.574,1504.982 3834.099,1504.982 3834.099,1505.882 3853.849,1505.882 3853.849,1504.982 3856.374,1504.982 3856.374,1501.482 3831.574,1501.482 ; 3925.724,1491.332 ccw(c3925.924,1491.332) 3925.924,1491.132 3930.024,1491.132 ccw(c3930.024,1491.332) 3930.224,1491.332 3930.224,1495.432 ccw(c3930.024,1495.432) 3930.024,1495.632 3925.924,1495.632 ccw(c3925.924,1495.432) 3925.724,1495.432 3925.724,1491.332 ; 3945.724,1491.332 ccw(c3945.924,1491.332) 3945.924,1491.132 3950.024,1491.132 ccw(c3950.024,1491.332) 3950.224,1491.332 3950.224,1495.432 ccw(c3950.024,1495.432) 3950.024,1495.632 3945.924,1495.632 ccw(c3945.924,1495.432) 3945.724,1495.432 3945.724,1491.332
